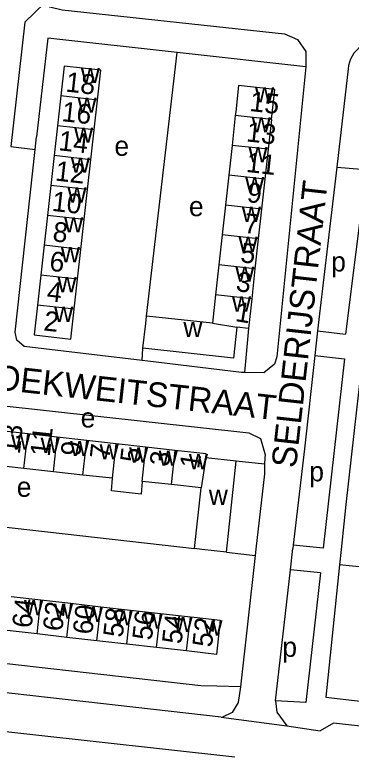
# Model space of a CAD drawing. Extents: x 161936 to 163647, y 386450 to 388633.
# Drawn here: x 162668.3 to 162736.4, y 387350.8 to 387499.8 of the extents above; entities that cross this region are included whole.
import ezdxf

# ---------------------------------------------------------------- set-up
doc = ezdxf.new("R2010")
doc.units = 0
for name, color, linetype in [('BLT_Basislijn', 7, 'Continuous'), ('BLT_Bebouwing', 7, 'Continuous'), ('BLT_Centroide', 7, 'Continuous'), ('BLT_Huisnummer', 7, 'Continuous'), ('BLT_Huisnummer_ tussenligend', 7, 'Continuous'), ('BLT_Onderverdeling_panden', 7, 'Continuous'), ('BLT_Straatnaam', 7, 'Continuous'), ('BLT_Vlakafsluiter', 7, 'Continuous')]:
    doc.layers.add(name, color=color, linetype=linetype)

msp = doc.modelspace()

# ---------------------------------------------------------------- linework, layer by layer
at = {"layer": 'BLT_Basislijn'}
for p, q in [((162670.29, 387498.35), (162674.4, 387502.25)), ((162670.29, 387498.35), (162667.46, 387473.15)), ((162694.94, 387438.85), (162701.15, 387492.22)), ((162735.77, 387488.88), (162733.44, 387469.03)), ((162672.44, 387472.59), (162672.71, 387475.13)), ((162667.46, 387473.15), (162672.44, 387472.59)), ((162733.44, 387469.03), (162729.96, 387439.33)), ((162729.96, 387439.33), (162729.57, 387435.87)), ((162715.56, 387436.33), (162714.75, 387427.45)), ((162729.57, 387435.87), (162729.01, 387430.9)), ((162729.57, 387435.87), (162735.21, 387435.19)), ((162694.06, 387429.89), (162694.23, 387432.38)), ((162729.01, 387430.9), (162734.98, 387430.18)), ((162734.98, 387430.18), (162730.71, 387391.85)), ((162718.85, 387408.89), (162713.1, 387409.49)), ((162643.3, 387398.77), (162704.64, 387391.8)), ((162724.06, 387387.5), (162724.56, 387391.83)), ((162724.63, 387392.46), (162724.56, 387391.83)), ((162730.71, 387391.85), (162724.63, 387392.46)), ((162734.34, 387391.62), (162734.01, 387388.49)), ((162711.1, 387391.1), (162716.93, 387390.43)), ((162716.93, 387390.43), (162713.94, 387363.79)), ((162734.01, 387388.49), (162731.21, 387361.69)), ((162739.27, 387387.94), (162734.01, 387388.49)), ((162721.05, 387361), (162724.06, 387387.5)), ((162730.13, 387386.88), (162724.06, 387387.5)), ((162710.05, 387357.7), (162588.35, 387371.46)), ((162713.94, 387363.79), (162709.16, 387363.93)), ((162731.21, 387361.69), (162852.86, 387347.9)), ((162723.33, 387355.95), (162730.11, 387354.92))]:
    msp.add_line(p, q, dxfattribs=at)
for points in [[(162674.4, 387502.25), (162675.36, 387501.47), (162677.9, 387500.85), (162722.89, 387495.99), (162725.51, 387494.85), (162727.19, 387492.41), (162727.19, 387489.31)], [(162701.15, 387492.22), (162674.96, 387495.08), (162672.71, 387475.13)], [(162742.29, 387494.29), (162741.61, 387494.34), (162740.93, 387494.31), (162740.26, 387494.2), (162739.61, 387494.02), (162738.99, 387493.76), (162738.4, 387493.42), (162737.85, 387493.02), (162737.35, 387492.56), (162736.91, 387492.04), (162736.54, 387491.48), (162736.23, 387490.87), (162736, 387490.24), (162735.84, 387489.58), (162735.77, 387488.88)], [(162727.19, 387489.31), (162701.72, 387492.16), (162701.15, 387492.22)], [(162727.19, 387489.31), (162721.29, 387430.63), (162720.82, 387429.12), (162718.65, 387427.36), (162714.75, 387427.45)], [(162694.06, 387429.89), (162670.2, 387432.71), (162668.7, 387433.99), (162668.39, 387435.58), (162672.44, 387472.59)], [(162733.44, 387469.03), (162738.42, 387468.59), (162739.23, 387467.47), (162735.21, 387435.19)], [(162739.8, 387440.64), (162737.4, 387419.86), (162735.26, 387400.7), (162734.34, 387391.62)], [(162729.01, 387430.9), (162726.9, 387412.01), (162724.63, 387392.46)], [(162714.75, 387427.45), (162714.19, 387427.47), (162695.23, 387429.75), (162694.06, 387429.89)], [(162655.11, 387421.92), (162715.68, 387415.23), (162718.03, 387414.06), (162718.96, 387410.77), (162718.89, 387410.16), (162718.85, 387408.89)], [(162718.85, 387408.89), (162718.8, 387406.93), (162717.08, 387391.68), (162716.93, 387390.43)], [(162730.13, 387386.88), (162727.21, 387360.63), (162721.05, 387361)], [(162709.16, 387363.93), (162705.92, 387364.03), (162600, 387376.06), (162594.64, 387376.67)], [(162713.94, 387363.79), (162713.52, 387360.64), (162712.27, 387358.65), (162710.17, 387357.6)], [(162721.05, 387361), (162721.32, 387358.67), (162723.33, 387355.95)], [(162657.23, 387355.77), (162712.78, 387349.62)], [(162846.77, 387343.8), (162732.81, 387356.45), (162730.11, 387354.92)]]:
    msp.add_lwpolyline(points, dxfattribs=at)
at = {"layer": 'BLT_Bebouwing'}
for p, q in [((162677.59, 387483.43), (162676.91, 387477.38)), ((162684.37, 387476.55), (162685.04, 387482.59)), ((162712.91, 387479.46), (162712.25, 387473.41)), ((162720.21, 387478.66), (162719.55, 387472.61)), ((162676.91, 387477.38), (162676.24, 387471.33)), ((162683.69, 387470.5), (162684.37, 387476.55)), ((162712.25, 387473.41), (162711.58, 387467.37)), ((162719.55, 387472.61), (162718.88, 387466.57)), ((162676.24, 387471.33), (162675.56, 387465.28)), ((162683.02, 387464.45), (162683.69, 387470.5)), ((162711.58, 387467.37), (162710.92, 387461.32)), ((162718.88, 387466.57), (162718.22, 387460.52)), ((162675.56, 387465.28), (162674.89, 387459.23)), ((162682.34, 387458.4), (162683.02, 387464.45)), ((162710.92, 387461.32), (162710.25, 387455.27)), ((162718.22, 387460.52), (162717.55, 387454.47)), ((162674.89, 387459.23), (162674.21, 387453.18)), ((162681.67, 387452.35), (162682.34, 387458.4)), ((162710.25, 387455.27), (162709.59, 387449.23)), ((162717.55, 387454.47), (162716.89, 387448.42)), ((162674.21, 387453.18), (162673.54, 387447.13)), ((162680.99, 387446.3), (162681.67, 387452.35)), ((162709.59, 387449.23), (162708.92, 387443.18)), ((162716.89, 387448.42), (162716.22, 387442.38)), ((162673.54, 387447.13), (162672.86, 387441.08)), ((162680.31, 387440.25), (162680.99, 387446.3)), ((162708.92, 387443.18), (162708.29, 387437.39)), ((162716.22, 387442.38), (162715.56, 387436.33)), ((162708.29, 387437.39), (162694.94, 387438.85)), ((162715.56, 387436.33), (162713.22, 387436.59)), ((162670.91, 387415.01), (162664.94, 387415.67)), ((162676.88, 387414.34), (162670.91, 387415.01)), ((162682.85, 387413.68), (162676.88, 387414.34)), ((162688.82, 387413.01), (162682.85, 387413.68)), ((162694.8, 387412.35), (162688.82, 387413.01)), ((162700.77, 387411.68), (162694.8, 387412.35)), ((162713.1, 387409.49), (162706.93, 387410.16)), ((162711.1, 387391.1), (162713.1, 387409.49)), ((162670.15, 387407.99), (162664.17, 387408.65)), ((162676.12, 387407.34), (162670.15, 387407.99)), ((162682.09, 387406.69), (162676.12, 387407.34)), ((162688.06, 387406.04), (162682.09, 387406.69)), ((162700.01, 387404.74), (162694.04, 387405.39)), ((162705.97, 387404.09), (162700.01, 387404.74)), ((162704.64, 387391.8), (162705.97, 387404.09)), ((162667.54, 387382.09), (162673.58, 387381.41)), ((162673.58, 387381.41), (162679.63, 387380.72)), ((162679.63, 387380.72), (162685.68, 387380.04)), ((162685.68, 387380.04), (162691.73, 387379.36)), ((162691.73, 387379.36), (162697.77, 387378.68)), ((162697.77, 387378.68), (162703.82, 387377.99)), ((162672.8, 387374.51), (162666.75, 387375.19)), ((162678.85, 387373.82), (162672.8, 387374.51)), ((162684.9, 387373.13), (162678.85, 387373.82)), ((162690.94, 387372.45), (162684.9, 387373.13)), ((162696.99, 387371.76), (162690.94, 387372.45)), ((162703.04, 387371.07), (162696.99, 387371.76))]:
    msp.add_line(p, q, dxfattribs=at)
for points in [[(162685.72, 387488.64), (162678.27, 387489.47), (162677.59, 387483.43)], [(162685.04, 387482.59), (162685.72, 387488.64)], [(162720.21, 387478.66), (162720.88, 387484.7), (162713.58, 387485.5), (162712.99, 387480.18), (162712.91, 387479.46)], [(162672.86, 387441.08), (162672.18, 387435.03), (162679.64, 387434.2), (162680.31, 387440.25)], [(162694.23, 387432.38), (162694.78, 387437.35), (162694.94, 387438.85)], [(162713.22, 387436.59), (162712.53, 387430.36), (162694.23, 387432.38)], [(162706.93, 387410.16), (162707.03, 387410.99), (162700.77, 387411.68)], [(162694.04, 387405.39), (162693.87, 387402.82), (162687.83, 387403.51), (162688.06, 387406.04)], [(162711.1, 387391.1), (162706.13, 387391.64), (162704.64, 387391.8)], [(162703.82, 387377.99), (162704.6, 387377.91), (162709.87, 387377.31), (162709.08, 387370.39), (162703.04, 387371.07)]]:
    msp.add_lwpolyline(points, dxfattribs=at)
at = {"layer": 'BLT_Onderverdeling_panden'}
for p, q in [((162685.04, 387482.59), (162677.59, 387483.43)), ((162720.21, 387478.66), (162712.91, 387479.46)), ((162684.37, 387476.55), (162676.91, 387477.38)), ((162719.55, 387472.61), (162712.25, 387473.41)), ((162683.69, 387470.5), (162676.24, 387471.33)), ((162718.88, 387466.57), (162711.58, 387467.37)), ((162683.02, 387464.45), (162675.56, 387465.28)), ((162718.22, 387460.52), (162710.92, 387461.32)), ((162682.34, 387458.4), (162674.89, 387459.23)), ((162717.55, 387454.47), (162710.25, 387455.27)), ((162681.67, 387452.35), (162674.21, 387453.18)), ((162716.89, 387448.42), (162709.59, 387449.23)), ((162680.99, 387446.3), (162673.54, 387447.13)), ((162716.22, 387442.38), (162708.92, 387443.18)), ((162680.31, 387440.25), (162672.86, 387441.08)), ((162708.29, 387437.39), (162713.22, 387436.59)), ((162670.15, 387407.99), (162670.91, 387415.01)), ((162676.12, 387407.34), (162676.88, 387414.34)), ((162682.09, 387406.69), (162682.85, 387413.68)), ((162688.06, 387406.04), (162688.82, 387413.01)), ((162694.04, 387405.39), (162694.8, 387412.35)), ((162700.01, 387404.74), (162700.77, 387411.68)), ((162706.93, 387410.16), (162705.97, 387404.09)), ((162672.8, 387374.51), (162673.58, 387381.41)), ((162678.85, 387373.82), (162679.63, 387380.72)), ((162684.9, 387373.13), (162685.68, 387380.04)), ((162690.94, 387372.45), (162691.73, 387379.36)), ((162696.99, 387371.76), (162697.77, 387378.68)), ((162703.04, 387371.07), (162703.82, 387377.99))]:
    msp.add_line(p, q, dxfattribs=at)
at = {"layer": 'BLT_Vlakafsluiter'}
msp.add_line((162710.05, 387357.7), (162723.33, 387355.95), dxfattribs=at)

# ---------------------------------------------------------------- texts
at = {"layer": 'BLT_Centroide'}
for s, p in [('w', (162681.65, 387486.03)), ('w', (162716.9, 387482.09)), ('w', (162680.98, 387480)), ('w', (162716.23, 387476.03)), ('w', (162680.3, 387473.94)), ('e', (162688.45, 387471.29)), ('w', (162715.57, 387470)), ('w', (162679.63, 387467.88)), ('w', (162714.9, 387463.94)), ('w', (162678.95, 387461.84)), ('e', (162703.53, 387459.07)), ('w', (162714.23, 387457.91)), ('w', (162678.27, 387455.78)), ('w', (162713.57, 387451.84)), ('w', (162677.6, 387449.75)), ('p', (162732.31, 387447.88)), ('w', (162712.91, 387445.81)), ('w', (162676.93, 387443.69)), ('w', (162712.24, 387439.75)), ('w', (162676.25, 387437.66)), ('w', (162702.4, 387434.59)), ('e', (162681.62, 387416.3)), ('w', (162667.55, 387411.83)), ('w', (162673.52, 387411.17)), ('w', (162679.48, 387410.52)), ('w', (162685.45, 387409.84)), ('w', (162691.42, 387409.2)), ('w', (162697.41, 387408.55)), ('w', (162703.52, 387407.86)), ('p', (162727.88, 387405.41)), ('e', (162668.69, 387402.28)), ('w', (162707.54, 387400.64)), ('w', (162670.17, 387378.3)), ('w', (162676.22, 387377.61)), ('w', (162682.27, 387376.94)), ('w', (162688.31, 387376.25)), ('w', (162694.36, 387375.56)), ('w', (162700.41, 387374.88)), ('w', (162706.45, 387374.19)), ('p', (162722.43, 387369.88))]:
    msp.add_text(s, height=4, dxfattribs=at).set_placement(p)
at = {"layer": 'BLT_Huisnummer'}
for s, rotation, p in [('18', 353.6261, (162678.45, 387484.32)), ('15', 353.7244, (162715.68, 387480.38)), ('14', 353.6252, (162677, 387472.44)), ('9', 353.7313, (162715.11, 387461.96)), ('10', 353.6252, (162675.66, 387460.17)), ('5', 353.7313, (162713.82, 387449.76)), ('6', 353.6311, (162675.17, 387448.05)), ('1', 350.7978, (162712.75, 387437.86)), ('2', 353.6387, (162674.01, 387435.97)), ('13', 83.7762, (162669.3, 387410.8)), ('9', 83.7771, (162681.52, 387410.38)), ('5', 83.781, (162693.56, 387409.09)), ('1', 81.008, (162705.56, 387407.8)), ('60', 83.5195, (162683.96, 387374.28)), ('56', 83.5233, (162696.01, 387373.12)), ('52', 83.5164, (162708.16, 387371.71))]:
    msp.add_text(s, height=4, rotation=rotation, dxfattribs=at).set_placement(p)
at = {"layer": 'BLT_Huisnummer_ tussenligend'}
for s, rotation, p in [('16', 353.6252, (162677.65, 387478.33)), ('13', 353.7313, (162715.02, 387474.23)), ('11', 353.7313, (162714.98, 387468.05)), ('12', 353.6252, (162676.33, 387466.3)), ('7', 353.7313, (162714.54, 387455.73)), ('8', 353.6311, (162675.83, 387454.03)), ('3', 350.7978, (162712.88, 387443.99)), ('4', 353.6387, (162674.65, 387441.94)), ('11', 83.7771, (162675.35, 387410.32)), ('7', 83.781, (162687.42, 387409.82)), ('3', 81.008, (162699.44, 387408.25)), ('64', 83.5195, (162671.68, 387375.58)), ('62', 83.5195, (162677.9, 387374.94)), ('58', 83.5233, (162690.12, 387373.7)), ('54', 83.5164, (162702.02, 387372.36))]:
    msp.add_text(s, height=4, rotation=rotation, dxfattribs=at).set_placement(p)
at = {"layer": 'BLT_Straatnaam'}
for s, rotation, p in [('SELDERIJSTRAAT', 83.6813, (162725.18, 387407.97)), ('BOEKWEITSTRAAT', 353.6941, (162659.59, 387424.57))]:
    msp.add_text(s, height=5, rotation=rotation, dxfattribs=at).set_placement(p)

doc.saveas('drawing.dxf')
